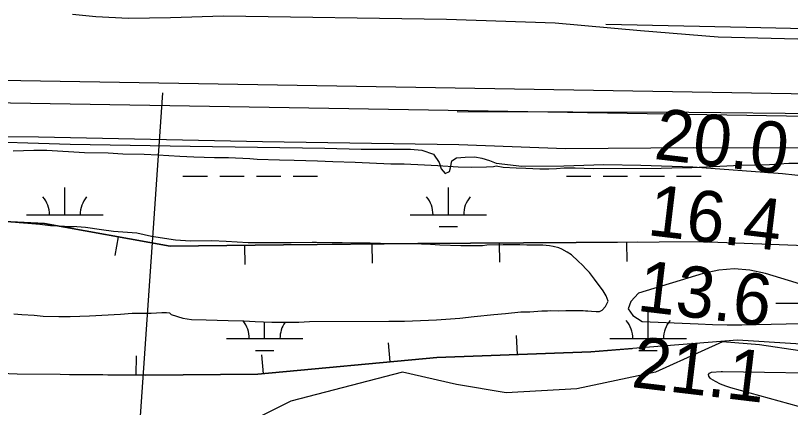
# Model space of a CAD drawing. Extents: x 3445503 to 3483459, y 540493 to 566012.
# Drawn here: x 3466718 to 3467732, y 552997 to 553510 of the extents above; entities that cross this region are included whole.
import ezdxf

# ---------------------------------------------------------------- set-up
doc = ezdxf.new("R2010")
doc.units = 0
for name, color, linetype in [('V-BORW-LINE', 7, 'Continuous'), ('V-FLOD-BASE', 7, 'Continuous'), ('V-LEVE-TOET', 7, 'Continuous'), ('V-RIVR-RANG', 7, 'Continuous'), ('V-SITE-VEGE', 7, 'Continuous'), ('V-SURV-LINE', 7, 'Continuous'), ('V-TOPO-MINR', 7, 'Continuous'), ('V-TOPO-SHOR', 7, 'Continuous'), ('V-WETL-SWMP', 7, 'Continuous')]:
    doc.layers.add(name, color=color, linetype=linetype)

msp = doc.modelspace()

# ---------------------------------------------------------------- linework, layer by layer
at = {"layer": 'V-BORW-LINE'}
for p, q in [((3466852.6, 553220.1), (3466848.1, 553195.5)), ((3467184.7, 553210.6), (3467185, 553185.6)), ((3467351.3, 553211.9), (3467351.4, 553186.9)), ((3467517.9, 553213), (3467518.1, 553188)), ((3467018.1, 553208.8), (3467018.4, 553183.8)), ((3467375, 553066), (3467374, 553090.9)), ((3467208.7, 553056.3), (3467206.4, 553081.2)), ((3466876.2, 553039.2), (3466876.4, 553064.2)), ((3467042.8, 553040.9), (3467040.5, 553065.8))]:
    msp.add_line(p, q, dxfattribs=at)
for points in [[(3466587.7, 553245.6), (3466756, 553237.7), (3466920.6, 553207.7), (3467069, 553209.4), (3467244.6, 553211.3), (3467452.1, 553212.5), (3467614.6, 553213.8), (3467820.4, 553206.3), (3467985.8, 553205.8), (3468130.9, 553216.9), (3468190.7, 553204.5), (3468230, 553140.6)], [(3467532, 553213.1), (3467452.1, 553212.5), (3467244.6, 553211.3), (3467069, 553209.4), (3466920.6, 553207.7), (3466756, 553237.7), (3466587.7, 553245.6)], [(3468230, 553140.6), (3468230.4, 553124.6), (3468233.5, 553084.1), (3468199, 553075.3), (3468011.2, 553075.4), (3467822.5, 553074.9), (3467663, 553084.8), (3467471.3, 553069.6), (3467269.8, 553062), (3467035.3, 553040.2), (3466888.6, 553039.1), (3466720.3, 553040.4), (3466609.1, 553044.9)], [(3466788.9, 553039.8), (3466888.6, 553039.1), (3467035.3, 553040.2), (3467269.8, 553062), (3467471.3, 553069.6), (3467525.2, 553073.9)]]:
    msp.add_lwpolyline(points, dxfattribs=at)
at = {"layer": 'V-FLOD-BASE'}
msp.add_lwpolyline([(3467296.4, 553384.3), (3467599.3, 553383.2), (3467935.1, 553379.8), (3468277.8, 553371.5), (3468393.7, 553367.7)], dxfattribs=at)
at = {"layer": 'V-LEVE-TOET'}
for points in [[(3466792.8, 553511.3), (3466823.4, 553508.2), (3466866.3, 553506.4), (3466921, 553507.2), (3466990.6, 553509.3), (3467282.1, 553505), (3467424.6, 553500.2)], [(3467424.6, 553500.2), (3467536, 553490.2), (3467637.7, 553481.6), (3467829, 553477), (3468019.4, 553476.2), (3468151.9, 553471), (3468203.7, 553468.3), (3468226, 553469.4), (3468250.8, 553470.3), (3468285.6, 553470.6), (3468376.3, 553465.9), (3468455.3, 553461.1), (3468534.3, 553450.1), (3468603.4, 553430.5), (3468692.7, 553394.1)], [(3465299.6, 553374.1), (3465570.2, 553371.6), (3465904, 553367.4), (3466118.7, 553359.5), (3466257.3, 553350.8), (3466425.8, 553352.6), (3466748.5, 553351), (3467041.3, 553344.7), (3467298.3, 553340.9)], [(3467298.3, 553340.9), (3467438.1, 553335.8), (3467605.3, 553337.1), (3467796.5, 553336.7), (3468025.1, 553333.4), (3468208.5, 553332.2), (3468274.4, 553336), (3468313.1, 553337.6), (3468327.3, 553338.3), (3468339.6, 553334.6), (3468344.9, 553331.2), (3468344.3, 553322.8), (3468345, 553311.8), (3468356.6, 553310.6), (3468397.3, 553316.1), (3468434.7, 553327.4), (3468472.8, 553327.7), (3468498.6, 553324), (3468579, 553287.2), (3468722.2, 553220.5)]]:
    msp.add_lwpolyline(points, dxfattribs=at)
at = {"layer": 'V-RIVR-RANG'}
msp.add_line((3466910.4, 553408.4), (3466815.3, 552031.7), dxfattribs=at)
at = {"layer": 'V-SITE-VEGE'}
for points in [[(3466715.2, 553332.6), (3466742.1, 553333.3), (3466759.4, 553333.4), (3466808.4, 553330.4), (3466839.3, 553329.8), (3466858.6, 553328.9), (3466886.7, 553328.4)], [(3466886.7, 553328.4), (3466904.4, 553327.5), (3466933.1, 553325.7), (3466951.7, 553324.8), (3466978.6, 553323.9), (3466996.9, 553323.7), (3467025, 553322.5), (3467034.5, 553321.6), (3467063.5, 553320.7), (3467083.1, 553320.4), (3467113.4, 553319.6), (3467133.6, 553318.7), (3467162.7, 553317.8), (3467209.4, 553315.8), (3467226.8, 553315.5), (3467253.3, 553314.3), (3467271, 553313.4), (3467297.5, 553311.6), (3467314.5, 553311.3), (3467334.4, 553311.7), (3467343.6, 553312.1), (3467347.1, 553313), (3467356.2, 553311.1), (3467373.6, 553310.2), (3467386.2, 553310), (3467404.2, 553309.1), (3467416.2, 553309.1), (3467426.3, 553309.5), (3467436.1, 553310.4), (3467450.6, 553310.5), (3467474.3, 553309.6), (3467563.3, 553309.9), (3467577.2, 553310.5), (3467596.8, 553310.9), (3467603.1, 553310.9), (3467622.4, 553311.6), (3467666.6, 553313.9), (3467705.1, 553314.7), (3467730.3, 553316.3), (3467748.6, 553316.4)], [(3467460, 553182.9), (3467454.6, 553188.3), (3467446, 553196.5), (3467440.3, 553199.9), (3467433.1, 553204), (3467429.3, 553205.6), (3467422, 553207.4), (3467416.9, 553208.4), (3467408.1, 553209.3), (3467387.3, 553209.2), (3467378.1, 553209.5), (3467356.3, 553209.5), (3467334.8, 553209.1), (3467329.5, 553208.4), (3467301.1, 553208.4), (3467273.3, 553209.2), (3467261.3, 553210.1), (3467249.3, 553210.4), (3467238.2, 553211), (3467209.2, 553210.9), (3467182.3, 553211.8), (3467159, 553211.7), (3467145.7, 553212.3), (3467132.5, 553212.3), (3467112.3, 553212.5), (3467106.6, 553212.5), (3467078.8, 553212.1), (3467022.9, 553212), (3466993.8, 553214.1), (3466975.2, 553214.7), (3466947.4, 553214.6), (3466927.5, 553215.5), (3466896.3, 553220.4), (3466877, 553224.8), (3466846.4, 553227.2), (3466830.9, 553229.1), (3466809.7, 553232.2), (3466798.4, 553233.1), (3466782.3, 553233.4), (3466763.9, 553234.6), (3466750, 553236.1), (3466734.3, 553237.3), (3466723.2, 553238.6), (3466712.8, 553239.2)], [(3466716, 553119.5), (3466726.7, 553118.6), (3466742.8, 553117.4), (3466754.5, 553116.1), (3466775, 553115.6), (3466789.9, 553115.6), (3466815.1, 553116.6), (3466855.8, 553119), (3466870.7, 553120), (3466883.9, 553120.3), (3466895.6, 553120.3), (3466909.5, 553121), (3466915.8, 553121), (3466919.6, 553120.4), (3466922.1, 553118.5), (3466937, 553113.5), (3466948.7, 553112), (3466967.6, 553111.4), (3466982.2, 553111.1), (3466996.4, 553110.5), (3467017.2, 553110), (3467031.7, 553109.1), (3467053.8, 553108.2), (3467068.4, 553108.2), (3467089.2, 553108.6), (3467103.1, 553109.3), (3467206.6, 553109.6), (3467227.2, 553109.9), (3467269.1, 553111.3), (3467299.5, 553113.6), (3467318.4, 553115.6), (3467344.3, 553118.5), (3467359.4, 553119.8), (3467379.3, 553121.8), (3467391.3, 553122.1), (3467406.8, 553123.1), (3467414.3, 553123.4), (3467418.1, 553123.5), (3467428.6, 553123.2), (3467438.3, 553123.5), (3467461.1, 553123.6), (3467464.2, 553123.3), (3467467.4, 553123.3), (3467471.8, 553122.7), (3467478.1, 553122.4), (3467482.5, 553122.4), (3467486, 553124), (3467490.4, 553128.7), (3467493.6, 553135.7), (3467491, 553142.9), (3467487.2, 553149.2), (3467476.1, 553164.7), (3467469.5, 553173.2), (3467464.4, 553178.2), (3467460, 553182.9)]]:
    msp.add_lwpolyline(points, dxfattribs=at)
at = {"layer": 'V-SURV-LINE'}
for points in [[(3464863.3, 553456.1), (3468482.7, 553395.2)], [(3468482.2, 553365.2), (3464862.7, 553426.1)]]:
    msp.add_lwpolyline(points, dxfattribs=at)
at = {"layer": 'V-TOPO-MINR'}
for points in [[(3467841.3, 553128.8), (3467699.6, 553172.1), (3467679.3, 553176.4), (3467658.9, 553178.2), (3467638.6, 553176.4), (3467618.3, 553172.1), (3467533.3, 553146.2), (3467523.5, 553135.5), (3467520, 553125.7), (3467525.9, 553117), (3467538.1, 553109.1), (3467611.5, 553106.1), (3467630.5, 553105.5), (3467649.6, 553105.1), (3467668.6, 553105.1), (3467687.6, 553105.3), (3467786.2, 553107.4)], [(3467919.8, 552949), (3467654.5, 553022.4), (3467647.6, 553024.7), (3467640.9, 553027.4), (3467634.4, 553030.6), (3467628.2, 553034.3), (3467627.1, 553035), (3467625.6, 553037.6), (3467625.2, 553039.8), (3467626.6, 553041.6), (3467629.2, 553043), (3467641.7, 553043.8), (3467642.1, 553043.8), (3467642.9, 553043.8), (3467643.3, 553043.8), (3467973.9, 553038.6)]]:
    msp.add_lwpolyline(points, dxfattribs=at)
at = {"layer": 'V-TOPO-SHOR'}
msp.add_lwpolyline([(3467490.9, 553498.5), (3467674.3, 553494.6), (3467887.5, 553489.8), (3468090.9, 553489.5), (3468181.2, 553490.1)], dxfattribs=at)
at = {"layer": 'V-WETL-SWMP'}
for p, q in [((3466937.4, 553299.6), (3466969.4, 553299.6)), ((3466985.4, 553299.6), (3467017.4, 553299.6)), ((3467033.4, 553299.6), (3467065.4, 553299.6)), ((3467081.4, 553299.6), (3467113.4, 553299.6)), ((3467439.3, 553299.6), (3467471.3, 553299.6)), ((3467487.3, 553299.6), (3467519.3, 553299.6)), ((3467535.3, 553299.6), (3467567.3, 553299.6)), ((3467583.3, 553299.6), (3467615.3, 553299.6)), ((3466782.8, 553248.8), (3466782.8, 553284.8)), ((3467284.7, 553248.8), (3467284.7, 553284.8)), ((3466732.8, 553248.8), (3466832.8, 553248.8)), ((3467234.7, 553248.8), (3467334.7, 553248.8)), ((3466782, 553233.4), (3466794.8, 553233.4)), ((3467272.7, 553233.4), (3467296.7, 553233.4)), ((3467713.2, 553133.4), (3467745.2, 553133.4)), ((3467546.1, 553087), (3467546.1, 553123)), ((3467044.2, 553087), (3467044.2, 553108.6)), ((3466994.2, 553087), (3467094.2, 553087)), ((3467496.1, 553087), (3467596.1, 553087)), ((3467032.2, 553071.5), (3467056.2, 553071.5)), ((3467534.1, 553071.5), (3467558.1, 553071.5))]:
    msp.add_line(p, q, dxfattribs=at)
for points in [[(3466651.1, 553345.9), (3466789.9, 553341.4), (3466946.9, 553338.7), (3467122.9, 553336.2), (3467170.5, 553334.7), (3467235.3, 553334.9), (3467250, 553333.7), (3467265.3, 553328.2), (3467272.5, 553317.4), (3467275.1, 553309), (3467280.7, 553302.8), (3467286.2, 553305.4), (3467287.5, 553310.3), (3467289.4, 553319.5), (3467295.3, 553323.4), (3467306.7, 553324.4), (3467319.4, 553324.8), (3467328.5, 553322.8), (3467338.3, 553319.9), (3467347.4, 553316.4), (3467380.6, 553312.5), (3467435.9, 553312.9), (3467488.3, 553314.7), (3467536.7, 553313.7), (3467604.4, 553311.5), (3467721.9, 553302.8), (3467770.2, 553297.6)], [(3467467.4, 553123.3), (3467471.8, 553122.7), (3467478.1, 553122.4), (3467482.5, 553122.4), (3467486, 553124), (3467490.4, 553128.7), (3467493.6, 553135.7), (3467491, 553142.9), (3467487.2, 553149.2), (3467476.1, 553164.7), (3467469.5, 553173.2), (3467464.4, 553178.2), (3467460, 553182.9), (3467454.6, 553188.3), (3467446, 553196.5), (3467440.3, 553199.9), (3467433.1, 553204), (3467429.3, 553205.6), (3467422, 553207.4), (3467416.9, 553208.4), (3467408.1, 553209.3), (3467387.3, 553209.2), (3467378.1, 553209.5), (3467356.3, 553209.5), (3467334.8, 553209.1), (3467329.5, 553208.4), (3467301.1, 553208.4), (3467273.3, 553209.2), (3467261.3, 553210.1), (3467249.3, 553210.4), (3467238.2, 553211), (3467209.2, 553210.9), (3467182.3, 553211.8), (3467159, 553211.7), (3467145.7, 553212.3), (3467132.5, 553212.3), (3467112.2, 553212.5), (3467106.6, 553212.5), (3467078.8, 553212.1), (3467022.9, 553212), (3466993.8, 553214.1), (3466975.2, 553214.7), (3466947.4, 553214.6), (3466927.5, 553215.5), (3466896.3, 553220.4), (3466877, 553224.8), (3466846.4, 553227.2), (3466830.9, 553229.1), (3466809.7, 553232.2), (3466798.4, 553233.1), (3466782.3, 553233.4), (3466763.9, 553234.6), (3466750, 553236.1), (3466734.3, 553237.3), (3466723.2, 553238.6), (3466712.8, 553239.2)], [(3466716, 553119.5), (3466726.7, 553118.6), (3466742.8, 553117.4), (3466754.5, 553116.1), (3466775, 553115.6), (3466789.9, 553115.6), (3466815.1, 553116.6), (3466855.8, 553119), (3466870.7, 553120), (3466883.9, 553120.3), (3466895.6, 553120.3), (3466909.5, 553121), (3466915.8, 553121), (3466919.6, 553120.4), (3466922.1, 553118.5), (3466937, 553113.5), (3466948.7, 553112), (3466967.6, 553111.4), (3466982.2, 553111.1), (3466996.4, 553110.5), (3467017.2, 553110), (3467031.7, 553109.1), (3467053.8, 553108.2), (3467068.4, 553108.2), (3467089.2, 553108.6), (3467103.1, 553109.3), (3467206.6, 553109.6), (3467227.2, 553109.9), (3467269.1, 553111.3), (3467299.5, 553113.6), (3467318.4, 553115.6), (3467344.3, 553118.5), (3467359.4, 553119.8), (3467379.3, 553121.8), (3467391.3, 553122.1), (3467406.8, 553123.1), (3467414.3, 553123.4), (3467418.1, 553123.5), (3467428.6, 553123.2), (3467438.3, 553123.5), (3467461.1, 553123.6), (3467464.2, 553123.3), (3467467.4, 553123.3)], [(3467744.4, 553070.9), (3467691.9, 553078.8), (3467643.5, 553082.5), (3467615.4, 553070.1), (3467555.8, 553042.9), (3467452.7, 553021.2), (3467360.5, 553015.8), (3467295.4, 553026.7), (3467224.8, 553042.9), (3467078.4, 553005), (3466948.2, 552939.9), (3466855.9, 552901.9), (3466742, 552896.5), (3466622.7, 552901.9)]]:
    msp.add_lwpolyline(points, dxfattribs=at)
for centre, start, end in [((3466727.5, 553249.3), 359.2282, 40.7719), ((3466838, 553249.3), 139.2282, 180.7718), ((3467229.4, 553249.3), 359.2282, 40.7719), ((3467339.9, 553249.3), 139.2282, 180.7718), ((3466989, 553087.4), 359.2282, 39.8602), ((3467490.9, 553087.4), 359.2282, 40.7719), ((3467601.4, 553087.4), 139.2282, 180.7718), ((3467099.5, 553087.4), 143.7062, 180.7718)]:
    msp.add_arc(centre, 35.2, start, end, dxfattribs=at)

# ---------------------------------------------------------------- texts
at = {"layer": 'V-RIVR-RANG'}
for s, p in [('20.0', (3467552.5, 553322.2)), ('16.4', (3467543.8, 553222.5)), ('13.6', (3467530.3, 553123.4)), ('21.1', (3467522.9, 553023.6))]:
    msp.add_text(s, height=67, rotation=353.1783, dxfattribs=at).set_placement(p)

doc.saveas('drawing.dxf')
